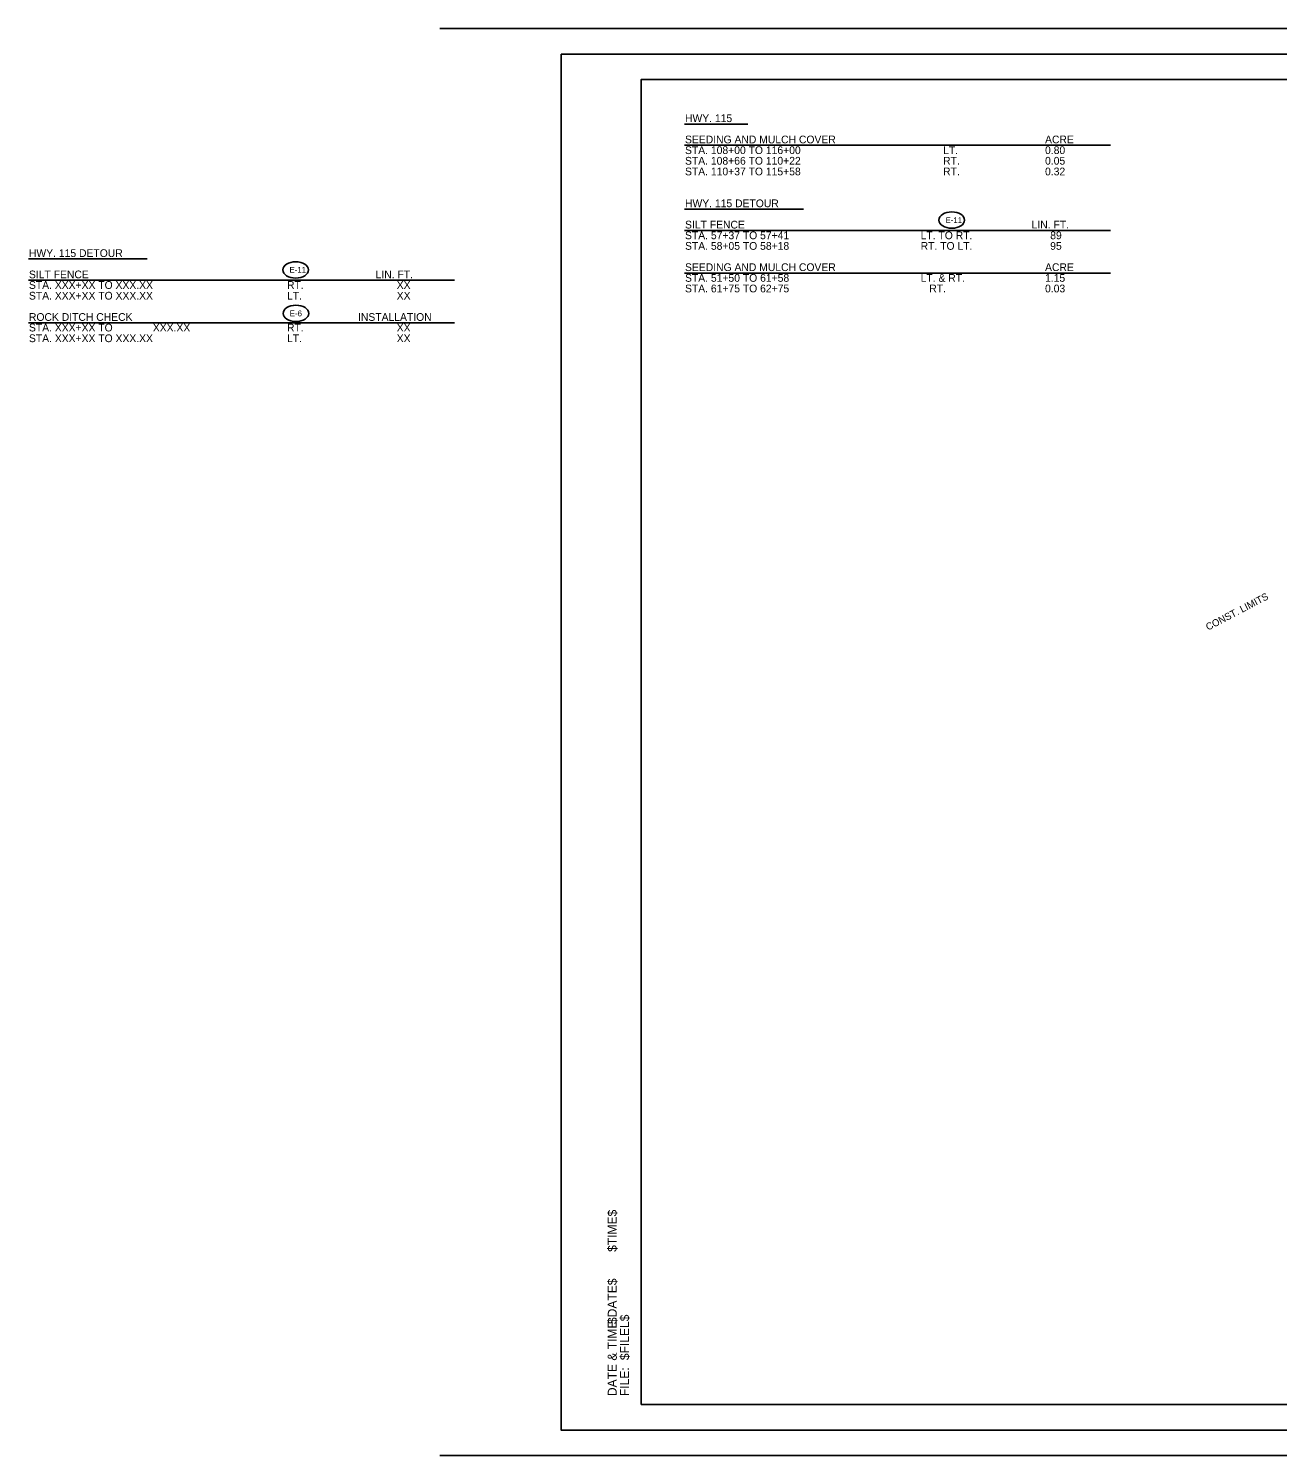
# Model space of a CAD drawing. Extents: x 9525 to 11605, y 9961 to 11067.
# Drawn here: x 9525 to 10493, y 9961 to 11067 of the extents above; entities that cross this region are included whole.
import ezdxf

# ---------------------------------------------------------------- set-up
doc = ezdxf.new("R2010")
doc.units = 0
for name, color, linetype in [('GREEN_TXT', 7, 'Continuous'), ('SEAL-INFO', 7, 'Continuous'), ('Stage 1 Ditch Checks', 7, 'Continuous'), ('Stage 2 Construction', 7, 'Continuous'), ('Stage 2 Flow Arrows', 7, 'Continuous')]:
    doc.layers.add(name, color=color, linetype=linetype)

msp = doc.modelspace()

# ---------------------------------------------------------------- linework, layer by layer
at = {"layer": 'GREEN_TXT'}
for p, q in [((11603.9, 11066.7), (9843.9, 11066.7)), ((10000, 11027.3), (11580.9, 11027.3)), ((10000, 10000), (10000, 11027.3)), ((11580.9, 10000), (10000, 10000)), ((9843.9, 9960.6), (11603.9, 9960.6))]:
    msp.add_line(p, q, dxfattribs=at)
at = {"layer": 'SEAL-INFO'}
msp.add_lwpolyline([(9938, 11046.8), (11604.7, 11046.8), (11604.7, 9980.1), (9938, 9980.1)], close=True, dxfattribs=at)
at = {"layer": 'Stage 1 Ditch Checks'}
msp.add_lwpolyline([(10000, 10000), (11580.9, 10000), (11580.3, 10963.3), (11365.4, 10963.3), (11357.3, 10959.9), (11348.5, 10961.4), (11348.3, 10977.9), (11169.6, 10977.9), (11169.6, 11027.3), (10000, 11027.3)], close=True, dxfattribs=at)
msp.add_lwpolyline([(10000, 10000), (11580.9, 10000), (11580.3, 10963.3), (11365.4, 10963.3), (11357.3, 10959.9), (11348.5, 10961.4), (11348.3, 10977.9), (11169.6, 10977.9), (11169.6, 11027.3), (10000, 11027.3)], close=True, dxfattribs=at)
at = {"layer": 'Stage 2 Construction'}
for p, q in [((10033.6, 10992.7), (10082.5, 10992.7)), ((10033.6, 10976.2), (10363.6, 10976.2)), ((10033.6, 10926.7), (10125.6, 10926.7)), ((10033.6, 10910.2), (10363.6, 10910.2)), ((10033.6, 10910.2), (10363.6, 10910.2)), ((9525.2, 10888.2), (9617.2, 10888.2)), ((10033.6, 10877.2), (10363.6, 10877.2)), ((9525.2, 10871.7), (9855.2, 10871.7)), ((9525.2, 10838.7), (9855.2, 10838.7))]:
    msp.add_line(p, q, dxfattribs=at)
for centre in [(10240.6, 10918.2), (9732.2, 10879.6), (9732.4, 10845.9)]:
    msp.add_ellipse(centre, major_axis=(9.94, 0), ratio=0.638788, dxfattribs=at)

# ---------------------------------------------------------------- texts
for s, height, p in [('$TIME$', 6.98, (9981, 10118.4)), ('$DATE$', 6.98, (9981, 10062.5)), ('DATE & TIME:', 6.984, (9981, 10006.6)), ('$FILEL$', 6.98, (9990.6, 10034.5)), ('FILE: ', 6.98, (9990.6, 10006.6))]:
    msp.add_text(s, height=height, rotation=90).set_placement(p)
for s, height, p in [('HWY. 115', 6, (10033.9, 10994.2)), ('SEEDING AND MULCH COVER', 6, (10033.9, 10977.7)), ('ACRE', 6, (10312.9, 10977.7)), ('STA. 108+00 TO 116+00', 6, (10033.9, 10969.4)), ('LT.', 6, (10233.9, 10969.4)), ('0.80', 6, (10312.9, 10969.4)), ('STA. 108+66 TO 110+22', 6, (10033.9, 10961.2)), ('RT.', 6, (10233.9, 10961.2)), ('0.05', 6, (10312.9, 10961.2)), ('STA. 110+37 TO 115+58', 6, (10033.9, 10952.9)), ('RT.', 6, (10233.9, 10952.9)), ('0.32', 6, (10312.9, 10952.9)), ('HWY. 115 DETOUR', 6, (10033.9, 10928.2)), ('SILT FENCE', 6, (10033.9, 10911.7)), ('E-11', 4.54, (10235.8, 10915.9)), ('LIN. FT.', 6, (10302.5, 10911.7)), ('STA. 57+37 TO 57+41', 6, (10033.9, 10903.4)), ('LT. TO RT.', 6, (10216.5, 10903.4)), ('89', 6, (10316.9, 10903.4)), ('HWY. 115 DETOUR', 6, (9525.5, 10889.6)), ('STA. 58+05 TO 58+18', 6, (10033.9, 10895.2)), ('RT. TO LT.', 6, (10216.5, 10895.2)), ('95', 6, (10316.9, 10895.2)), ('SEEDING AND MULCH COVER', 6, (10033.9, 10878.7)), ('ACRE', 6, (10312.9, 10878.7)), ('SILT FENCE', 6, (9525.5, 10873.1)), ('E-11', 4.54, (9727.4, 10877.4)), ('LIN. FT.', 6, (9794.1, 10873.1)), ('STA. 51+50 TO 61+58', 6, (10033.9, 10870.4)), ('LT. & RT.', 6, (10216.5, 10870.4)), ('1.15', 6, (10312.9, 10870.4)), ('STA. XXX+XX TO XXX.XX', 6, (9525.5, 10864.9)), ('STA. XXX+XX TO XXX.XX', 6, (9525.5, 10856.6)), ('RT.', 6, (9725.5, 10864.9)), ('LT.', 6, (9725.5, 10856.6)), ('XX', 6, (9810.5, 10864.9)), ('XX', 6, (9810.5, 10856.6)), ('STA. 61+75 TO 62+75', 6, (10033.9, 10862.2)), ('   RT.', 6, (10216.5, 10862.2)), ('0.03', 6, (10312.9, 10862.2)), ('ROCK DITCH CHECK', 6, (9525.5, 10840.1)), ('INSTALLATION', 6, (9780.5, 10840.1)), ('STA. XXX+XX TO', 6, (9525.5, 10831.9)), ('STA. XXX+XX TO XXX.XX', 6, (9525.5, 10823.6)), ('XXX.XX', 6, (9621.5, 10831.9)), ('RT.', 6, (9725.5, 10831.9)), ('LT.', 6, (9725.5, 10823.6)), ('XX', 6, (9810.5, 10831.9)), ('XX', 6, (9810.5, 10823.6))]:
    msp.add_text(s, height=height, dxfattribs=at).set_placement(p)
msp.add_text('E-6', height=4.54, rotation=360, dxfattribs=at).set_placement((9727.6, 10843.6))
at = {"layer": 'Stage 2 Flow Arrows'}
msp.add_text('CONST. LIMITS', height=5.5, rotation=27.6272, dxfattribs=at).set_placement((10439.2, 10599.9))

doc.saveas('drawing.dxf')
